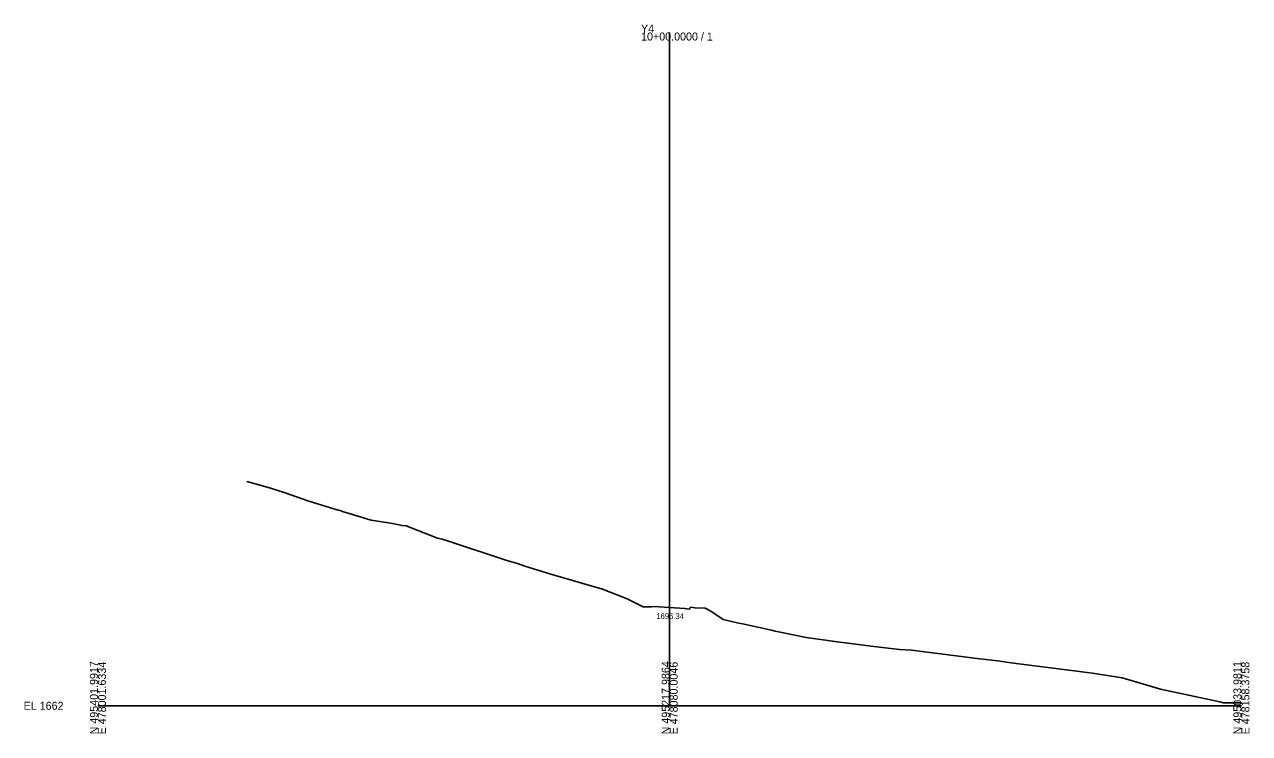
# Model space of a CAD drawing. Extents: x -26 to 403, y -10 to 5108.
# Drawn here: x -25.7 to 402.8, y -9.7 to 238.3 of the extents above; entities that cross this region are included whole.
import ezdxf

# ---------------------------------------------------------------- set-up
doc = ezdxf.new("R2010")
doc.units = 0
for name, color, linetype in [('Exist Cross Section Cell', 7, 'Continuous'), ('Exist XS Center Line Elevation Label', 7, 'Continuous'), ('Exist XS Ground Line', 7, 'Continuous')]:
    doc.layers.add(name, color=color, linetype=linetype)

msp = doc.modelspace()

# ---------------------------------------------------------------- linework, layer by layer
at = {"layer": 'Exist Cross Section Cell'}
for p, q in [((200, 0), (200, 235.53)), ((0, 0), (200, 0)), ((200, 0), (400, 0))]:
    msp.add_line(p, q, dxfattribs=at)
at = {"layer": 'Exist XS Ground Line'}
msp.add_lwpolyline([(52.08, 78.51), (59.99, 76.28), (62.95, 75.36), (65.16, 74.62), (73.83, 71.61), (84.09, 68.48), (84.7, 68.29), (85.51, 67.95), (95.57, 64.92), (103.03, 63.77), (106.44, 63.1), (107.81, 63), (118.76, 58.63), (120.4, 58.32), (122.67, 57.55), (142.69, 50.95), (147.12, 49.62), (149.39, 48.89), (158.43, 46), (176.52, 40.77), (185.09, 37.38), (190.72, 34.62), (193.61, 34.61), (194.5, 34.71), (200, 34.34), (205.33, 34.01), (206.08, 33.94), (206.84, 33.79), (207.16, 34.32), (207.46, 34.48), (208.8, 34.28), (212.46, 34.16), (214.4, 33.1), (218.71, 30.22), (223.64, 29.01), (226.02, 28.6), (235.59, 26.46), (236.9, 26.16), (238.66, 25.8), (247.77, 23.94), (254.53, 22.92), (258.64, 22.33), (264.18, 21.66), (269.51, 20.97), (273.46, 20.5), (280.38, 19.68), (282.59, 19.56), (284.62, 19.48), (308.46, 16.45), (314.71, 15.69), (319.46, 15.06), (322.18, 14.62), (347.97, 11.43), (358.24, 9.8), (371.72, 5.84), (392.43, 1.36), (393.8, 1.03), (394.62, 1.02), (395.19, 1.01), (400, 1)], dxfattribs=at)

# ---------------------------------------------------------------- texts
at = {"layer": 'Exist Cross Section Cell'}
for s, p in [('Y4', (190, 235.53)), ('10+00.0000 / 1', (190, 232.73)), ('EL 1662', (-26, -1.4))]:
    msp.add_text(s, height=2.8, dxfattribs=at).set_placement(p)
for s, p in [('N 495401.9917', (0, -10)), ('E 478001.6334', (2.8, -10)), ('N 495217.9864', (200, -10)), ('E 478080.0046', (202.8, -10)), ('N 495033.9811', (400, -10)), ('E 478158.3758', (402.8, -10))]:
    msp.add_text(s, height=2.8, rotation=90, dxfattribs=at).set_placement(p)
at = {"layer": 'Exist XS Center Line Elevation Label'}
msp.add_text('1696.34', height=2, dxfattribs=at).set_placement((195.34, 30.34))

doc.saveas('drawing.dxf')
